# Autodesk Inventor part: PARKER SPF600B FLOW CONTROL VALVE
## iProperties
Author: Tom Cross
Shininess: 54.0
Angle Display Precision: 2
Document Length Units: 11272
Document Angle Units: 11286
Document Time Units: 11279
Document Mass Units: 11290
Document Length Units Precision: 4
Document Angle Units Precision: 2
Compacted: True
PropertySet Name: _Private Model Information
Created: 2001-11
Part Number: PARKER SPF600B FLOW CONTROL VALVE
Material: Brass, Soft Yellow
Document SubType Name: Modeling
Designer: Administrator
Control State: 0
Master: False
Checked Out: False
PropertySet Name: Design Tracking Control
Density: 8.47
Volumn: 88.14423636474928
Area: 208.91871298874656
PropertySet Name: Model Information
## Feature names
1. Revolution1
2. Extrusion1
3. Revolution2
4. Revolution3
